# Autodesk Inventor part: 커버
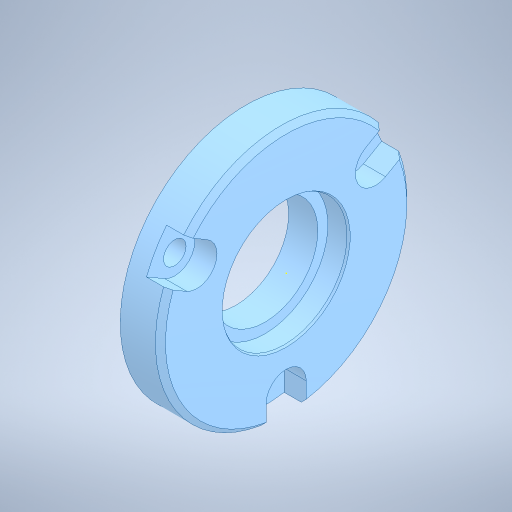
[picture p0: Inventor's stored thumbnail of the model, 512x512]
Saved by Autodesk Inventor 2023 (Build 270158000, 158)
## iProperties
Created: 2025-10
Part Number: 커버
Material: 알루미늄 6061
Document SubType Name: Modeling
Designer: home
Density: 2.7 g/cm^3
Appearance: 기본값
Author: jhkim
Sending System: Autodesk Inventor 2026
Preprocessor: ST-DEVELOPER v20.1
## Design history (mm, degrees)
sketch "스케치1"
  geometry: 1 further point
  constraints: 1 other
feature "솔리드1"
node "솔리드2"
